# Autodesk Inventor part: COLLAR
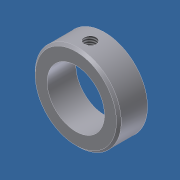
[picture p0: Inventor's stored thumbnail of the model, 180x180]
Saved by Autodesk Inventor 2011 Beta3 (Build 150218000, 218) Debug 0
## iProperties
Shininess: 64.0
Length Units: 11272
Angle Units: 11279
Time Units: 11290
Mass Units: 11286
Length Display Precision: 3
Angle Display Precision: 2
Compacted: True
Part Number: COLLAR
Document SubType Name: Modeling
Created: 2003-11
Designer: Autodesk, Inc.
Manufacturer: Standard
Standards Organization: Custom
Mass: 25.9974 g
Surface Area: 21.2895 cm^2
Volume: 3.30755 cm^3
Density: 7.86 g/cm^3
Material: Steel, Mild
Density: 0.0
Volumn: 0.0
Area: 0.0
PropertySet Name: Model Information
Control State: 0
Master: False
Checked Out: False
Author: Autodesk, Inc.
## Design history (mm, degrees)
sketch "Sketch1"
  geometry: C1 r 14.287 at (0, 0); C2 r 9.525 at (0, 0); 1 further point
  constraints: 2 centre point, 2 coincident
  dimensions: "d0" = 28.575 diameter of C1; "d1" = 19.05 diameter of C2
extrude "Extrusion1" new body sketch "Sketch1" distance "d2" = 9.525; taper "d3" = 0 deg
chamfer "Chamfer1" distance "d4" = 0.7874; stored, may be unused: second distance "d5" = 3.175, angle "d16" = 45 deg
sketch "Sketch3"
  geometry: L1 (-14.287, 0)-(14.287, 0) reference; L2 (14.287, 8.738)-(-14.287, 8.738) reference; L3 (14.287, 0)-(14.287, 8.738) reference; L4 (-14.287, 0)-(-14.287, 8.738) reference; L5 (0, 0)-(0, 8.738); 1 further point
  constraints: 2 end point, 2 midpoint, 1 point on line
  dimensions: "d8" = 4.7625 distance from line of L1 point (0, 4.763)
hole "Hole1" sketch "Sketch3" at (0, 4.763) diameter "d9" = 3.9624; stored, may be unused: countersink angle "d13" = 82 deg, drill point angle "d15" = 118 deg; dims "d10" = 12.7, "d11" = 9.525, "d12" = 6.35, "d14" = 19.05
body "Solid1"
